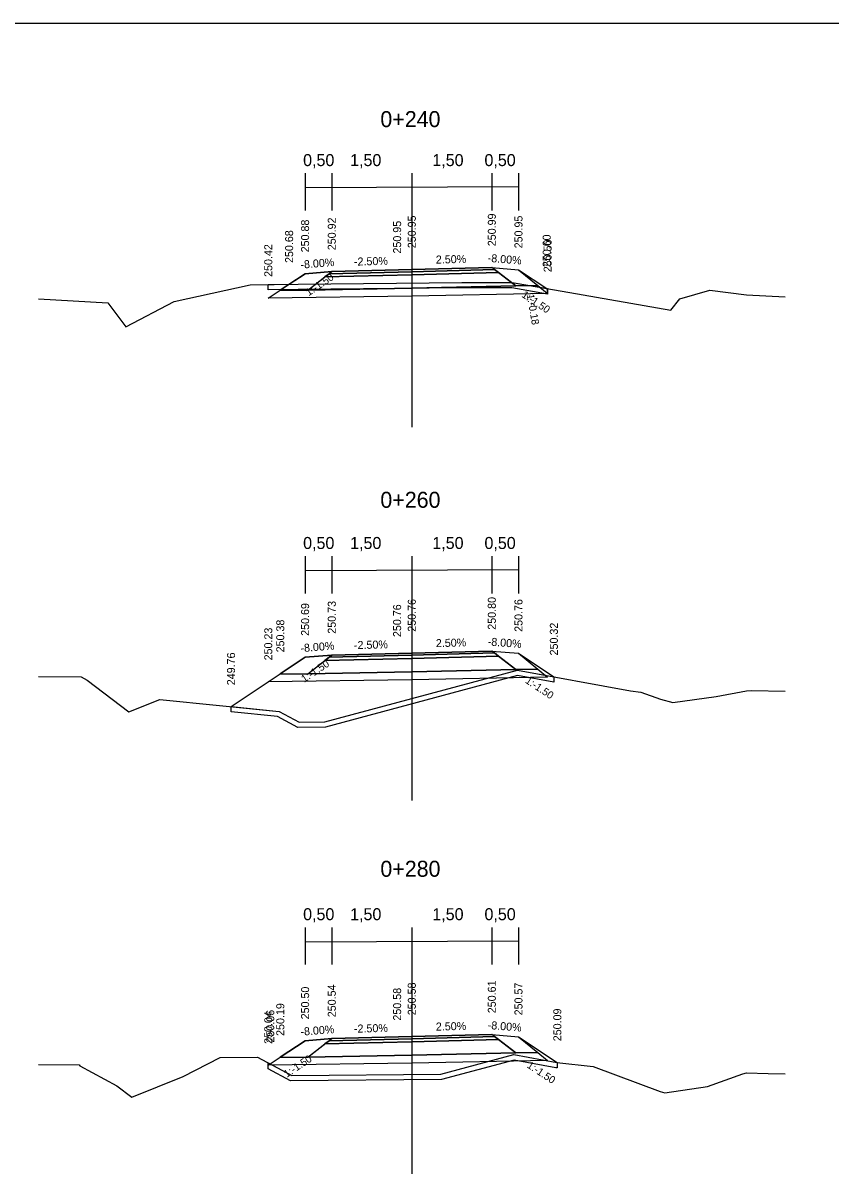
# Model space of a CAD drawing. Extents: x -552501 to -552394, y -1029983 to -1029892.
# Drawn here: x -552453.26 to -552438.12, y -1029914.92 to -1029893.35 of the extents above; entities that cross this region are included whole.
import ezdxf

# ---------------------------------------------------------------- set-up
doc = ezdxf.new("R2010")
doc.units = 0
for name, color, linetype in [('1', 7, 'Continuous'), ('16', 7, 'Continuous'), ('60', 7, 'Continuous'), ('9', 7, 'Continuous'), ('Implicitní', 7, 'Continuous'), ('rámeček', 7, 'Continuous')]:
    doc.layers.add(name, color=color, linetype=linetype)

msp = doc.modelspace()

# ---------------------------------------------------------------- linework, layer by layer
for points in [[(-552448.667, -1029898.509), (-552448.276, -1029898.248), (-552447.977, -1029898.049), (-552447.477, -1029898.009), (-552445.977, -1029897.971), (-552444.477, -1029897.934), (-552443.977, -1029897.974), (-552443.448, -1029898.327), (-552443.431, -1029898.421)], [(-552452.977, -1029898.522), (-552451.672, -1029898.595), (-552451.339, -1029899.045), (-552450.431, -1029898.568), (-552449.007, -1029898.258), (-552448.105, -1029898.245), (-552445.041, -1029898.212), (-552444.095, -1029898.216), (-552443.013, -1029898.401), (-552441.119, -1029898.731), (-552440.95, -1029898.523), (-552440.392, -1029898.359), (-552439.702, -1029898.447), (-552438.977, -1029898.481)], [(-552449.365, -1029906.163), (-552448.667, -1029905.697), (-552448.442, -1029905.547), (-552447.977, -1029905.237), (-552447.477, -1029905.197), (-552445.977, -1029905.16), (-552444.477, -1029905.122), (-552443.977, -1029905.162), (-552443.314, -1029905.604)], [(-552452.977, -1029905.602), (-552452.176, -1029905.605), (-552452.174, -1029905.608), (-552452.064, -1029905.667), (-552451.283, -1029906.264), (-552450.7, -1029906.029), (-552448.466, -1029906.253), (-552448.09, -1029906.455), (-552447.607, -1029906.451), (-552443.998, -1029905.478), (-552441.878, -1029905.87), (-552441.681, -1029905.892), (-552441.317, -1029906.027), (-552441.085, -1029906.089), (-552440.269, -1029905.973), (-552439.705, -1029905.868), (-552439.608, -1029905.862), (-552438.977, -1029905.875)], [(-552448.667, -1029912.886), (-552448.63, -1029912.861), (-552448.442, -1029912.736), (-552447.977, -1029912.426), (-552447.477, -1029912.386), (-552445.977, -1029912.349), (-552444.477, -1029912.311), (-552443.977, -1029912.351), (-552443.249, -1029912.836)], [(-552452.977, -1029912.875), (-552452.209, -1029912.877), (-552452.199, -1029912.898), (-552451.505, -1029913.27), (-552451.226, -1029913.483), (-552450.264, -1029913.095), (-552449.568, -1029912.74), (-552448.869, -1029912.733), (-552448.223, -1029913.08), (-552445.434, -1029913.056), (-552444.064, -1029912.686), (-552443.26, -1029912.835), (-552442.58, -1029912.912), (-552441.324, -1029913.377), (-552441.235, -1029913.401), (-552440.434, -1029913.286), (-552439.772, -1029913.045), (-552439.702, -1029913.026), (-552439.296, -1029913.041), (-552438.977, -1029913.049)]]:
    msp.add_lwpolyline(points)
for points in [[(-552445.978, -1029898.011), (-552447.528, -1029898.049), (-552447.606, -1029898.109), (-552445.978, -1029898.071), (-552444.349, -1029898.028), (-552444.426, -1029897.968), (-552445.978, -1029898.011), (-552444.426, -1029897.968), (-552444.477, -1029897.934), (-552445.977, -1029897.971), (-552447.477, -1029898.009), (-552447.528, -1029898.049)], [(-552444.477, -1029897.934), (-552443.977, -1029897.974), (-552443.616, -1029898.271), (-552444.027, -1029898.278), (-552444.349, -1029898.028), (-552444.426, -1029897.968)], [(-552447.477, -1029898.009), (-552447.977, -1029898.049), (-552448.442, -1029898.359), (-552447.928, -1029898.359)], [(-552447.928, -1029898.359), (-552447.606, -1029898.109), (-552445.978, -1029898.071), (-552444.349, -1029898.028), (-552444.027, -1029898.278), (-552445.978, -1029898.321)], [(-552447.606, -1029898.109), (-552447.528, -1029898.049), (-552445.978, -1029898.011), (-552444.426, -1029897.968), (-552444.349, -1029898.028), (-552445.978, -1029898.071)], [(-552448.667, -1029898.253), (-552448.105, -1029898.245), (-552445.041, -1029898.212), (-552444.095, -1029898.216), (-552443.431, -1029898.329), (-552443.431, -1029898.431), (-552444.104, -1029898.316), (-552445.04, -1029898.312), (-552448.104, -1029898.345), (-552448.667, -1029898.353)], [(-552448.667, -1029898.509), (-552448.442, -1029898.359), (-552447.928, -1029898.359), (-552445.978, -1029898.321), (-552444.027, -1029898.278), (-552443.616, -1029898.271), (-552443.431, -1029898.421), (-552445.978, -1029898.471)], [(-552447.477, -1029905.197), (-552447.977, -1029905.237), (-552448.442, -1029905.547), (-552447.928, -1029905.547)], [(-552447.928, -1029905.547), (-552447.606, -1029905.297), (-552445.978, -1029905.26), (-552444.349, -1029905.216), (-552444.027, -1029905.466), (-552445.978, -1029905.51)], [(-552445.978, -1029905.2), (-552447.528, -1029905.237), (-552447.606, -1029905.297), (-552445.978, -1029905.26), (-552444.349, -1029905.216), (-552444.426, -1029905.156), (-552445.978, -1029905.2), (-552444.426, -1029905.156), (-552444.477, -1029905.122), (-552445.977, -1029905.16), (-552447.477, -1029905.197), (-552447.528, -1029905.237)], [(-552447.606, -1029905.297), (-552447.528, -1029905.237), (-552445.978, -1029905.2), (-552444.426, -1029905.156), (-552444.349, -1029905.216), (-552445.978, -1029905.26)], [(-552444.477, -1029905.122), (-552443.977, -1029905.162), (-552443.616, -1029905.46), (-552444.027, -1029905.466), (-552444.349, -1029905.216), (-552444.426, -1029905.156)], [(-552449.365, -1029906.163), (-552448.466, -1029906.253), (-552448.09, -1029906.455), (-552447.607, -1029906.451), (-552443.998, -1029905.478), (-552443.314, -1029905.604), (-552443.314, -1029905.706), (-552443.993, -1029905.581), (-552447.593, -1029906.551), (-552448.115, -1029906.556), (-552448.496, -1029906.351), (-552449.365, -1029906.263)], [(-552448.667, -1029905.697), (-552448.442, -1029905.547), (-552447.928, -1029905.547), (-552445.978, -1029905.51), (-552444.027, -1029905.466), (-552443.616, -1029905.46), (-552443.431, -1029905.61), (-552445.978, -1029905.66)], [(-552447.477, -1029912.386), (-552447.977, -1029912.426), (-552448.442, -1029912.736), (-552447.928, -1029912.736)], [(-552447.928, -1029912.736), (-552447.606, -1029912.486), (-552445.978, -1029912.449), (-552444.349, -1029912.405), (-552444.027, -1029912.655), (-552445.978, -1029912.699)], [(-552445.978, -1029912.389), (-552447.528, -1029912.426), (-552447.606, -1029912.486), (-552445.978, -1029912.449), (-552444.349, -1029912.405), (-552444.426, -1029912.345), (-552445.978, -1029912.389), (-552444.426, -1029912.345), (-552444.477, -1029912.311), (-552445.977, -1029912.349), (-552447.477, -1029912.386), (-552447.528, -1029912.426)], [(-552447.606, -1029912.486), (-552447.528, -1029912.426), (-552445.978, -1029912.389), (-552444.426, -1029912.345), (-552444.349, -1029912.405), (-552445.978, -1029912.449)], [(-552444.477, -1029912.311), (-552443.977, -1029912.351), (-552443.616, -1029912.649), (-552444.027, -1029912.655), (-552444.349, -1029912.405), (-552444.426, -1029912.345)], [(-552448.667, -1029912.886), (-552448.442, -1029912.736), (-552447.928, -1029912.736), (-552445.978, -1029912.699), (-552444.027, -1029912.655), (-552443.616, -1029912.649), (-552443.431, -1029912.799), (-552445.978, -1029912.849)], [(-552448.667, -1029912.841), (-552448.223, -1029913.08), (-552445.434, -1029913.056), (-552444.064, -1029912.686), (-552443.26, -1029912.835), (-552443.249, -1029912.836), (-552443.249, -1029912.937), (-552443.275, -1029912.934), (-552444.06, -1029912.789), (-552445.421, -1029913.156), (-552448.248, -1029913.18), (-552448.667, -1029912.955)]]:
    msp.add_lwpolyline(points, close=True)
at = {"layer": '60'}
for p, q in [((-552445.977, -1029896.924), (-552445.977, -1029900.924)), ((-552445.977, -1029903.924), (-552445.977, -1029907.924)), ((-552445.977, -1029910.924), (-552445.977, -1029914.924))]:
    msp.add_line(p, q, dxfattribs=at)
at = {"layer": '9'}
for p, q in [((-552447.977, -1029896.167), (-552447.977, -1029896.865)), ((-552447.477, -1029896.167), (-552447.477, -1029896.865)), ((-552445.977, -1029896.167), (-552445.977, -1029897.667)), ((-552444.477, -1029896.167), (-552444.477, -1029896.865)), ((-552443.977, -1029896.167), (-552443.977, -1029896.865)), ((-552447.977, -1029903.344), (-552447.977, -1029904.042)), ((-552447.477, -1029903.344), (-552447.477, -1029904.042)), ((-552445.977, -1029903.344), (-552445.977, -1029904.844)), ((-552444.477, -1029903.344), (-552444.477, -1029904.042)), ((-552443.977, -1029903.344), (-552443.977, -1029904.042)), ((-552447.977, -1029910.303), (-552447.977, -1029911)), ((-552447.477, -1029910.303), (-552447.477, -1029911)), ((-552445.977, -1029910.303), (-552445.977, -1029911.803)), ((-552444.477, -1029910.303), (-552444.477, -1029911)), ((-552443.977, -1029910.303), (-552443.977, -1029911))]:
    msp.add_line(p, q, dxfattribs=at)
at = {"layer": 'Implicitní'}
for p, q in [((-552447.967, -1029896.435), (-552443.977, -1029896.417)), ((-552447.967, -1029903.612), (-552443.977, -1029903.594)), ((-552447.967, -1029910.57), (-552443.977, -1029910.553))]:
    msp.add_line(p, q, dxfattribs=at)
at = {"layer": 'rámeček'}
msp.add_line((-552499.755, -1029893.35), (-552394.755, -1029893.35), dxfattribs=at)

# ---------------------------------------------------------------- texts
for s, rotation, p in [('1:-1.50', 33.6902, (-552447.91, -1029898.473)), ('1:-1.50', 326.3098, (-552443.929, -1029898.475)), ('1:-0.18', 280.0484, (-552443.824, -1029898.442)), ('1:-1.50', 33.6901, (-552447.993, -1029905.717)), ('1:-1.50', 326.3098, (-552443.862, -1029905.708)), ('1:-1.50', 33.6902, (-552448.32, -1029913.123)), ('1:-1.50', 326.3098, (-552443.83, -1029912.918))]:
    msp.add_text(s, height=0.14, rotation=rotation).set_placement(p)
at = {"layer": '1'}
for s, p in [('0+240', (-552446.566, -1029895.301)), ('0+260', (-552446.566, -1029902.437)), ('0+280', (-552446.566, -1029909.353))]:
    msp.add_text(s, height=0.3, dxfattribs=at).set_placement(p)
at = {"layer": '16'}
for s, p in [('0,50', (-552448.014, -1029896.032)), ('1,50', (-552447.133, -1029896.032)), ('1,50', (-552445.592, -1029896.032)), ('0,50', (-552444.615, -1029896.032)), ('0,50', (-552448.014, -1029903.209)), ('1,50', (-552447.133, -1029903.209)), ('1,50', (-552445.592, -1029903.209)), ('0,50', (-552444.615, -1029903.209)), ('0,50', (-552448.014, -1029910.167)), ('1,50', (-552447.133, -1029910.167)), ('1,50', (-552445.592, -1029910.167)), ('0,50', (-552444.615, -1029910.167))]:
    msp.add_text(s, height=0.225, dxfattribs=at).set_placement(p)
for s, rotation, p in [('250.88', 90, (-552447.902, -1029897.649)), ('250.92', 90, (-552447.402, -1029897.609)), ('250.95', 90, (-552446.177, -1029897.671)), ('250.95', 90, (-552445.902, -1029897.571)), ('250.99', 90, (-552444.402, -1029897.534)), ('250.95', 90, (-552443.902, -1029897.574)), ('250.68', 90, (-552448.201, -1029897.848)), ('250.42', 90, (-552448.592, -1029898.109)), ('250.60', 90, (-552443.373, -1029897.927)), ('250.50', 90, (-552443.356, -1029898.021)), ('-2.50%', 1.4321, (-552447.059, -1029897.898)), ('2.50%', 1.4321, (-552445.524, -1029897.86)), ('-8.00%', 355.4261, (-552444.558, -1029897.827)), ('-8.00%', 4.5739, (-552448.058, -1029897.955)), ('250.73', 90, (-552447.402, -1029904.797)), ('250.76', 90, (-552445.902, -1029904.76)), ('250.80', 90, (-552444.402, -1029904.722)), ('250.76', 90, (-552443.902, -1029904.762)), ('250.69', 90, (-552447.902, -1029904.837)), ('250.76', 90, (-552446.177, -1029904.86)), ('250.38', 90, (-552448.367, -1029905.147)), ('250.32', 90, (-552443.239, -1029905.204)), ('250.23', 90, (-552448.592, -1029905.297)), ('-8.00%', 4.5739, (-552448.058, -1029905.144)), ('-2.50%', 1.4321, (-552447.059, -1029905.087)), ('2.50%', 1.4321, (-552445.524, -1029905.049)), ('-8.00%', 355.4261, (-552444.558, -1029905.016)), ('249.76', 90, (-552449.29, -1029905.763)), ('250.61', 90, (-552444.402, -1029911.911)), ('250.50', 90, (-552447.902, -1029912.026)), ('250.54', 90, (-552447.402, -1029911.986)), ('250.58', 90, (-552446.177, -1029912.049)), ('250.58', 90, (-552445.902, -1029911.949)), ('250.57', 90, (-552443.902, -1029911.951)), ('250.19', 90, (-552448.367, -1029912.336)), ('250.04', 90, (-552448.592, -1029912.486)), ('250.06', 90, (-552448.555, -1029912.461)), ('250.09', 90, (-552443.174, -1029912.436)), ('-8.00%', 4.5739, (-552448.058, -1029912.333)), ('-2.50%', 1.4321, (-552447.059, -1029912.276)), ('2.50%', 1.4321, (-552445.524, -1029912.237)), ('-8.00%', 355.4261, (-552444.558, -1029912.205))]:
    msp.add_text(s, height=0.15, rotation=rotation, dxfattribs=at).set_placement(p)

doc.saveas('drawing.dxf')
